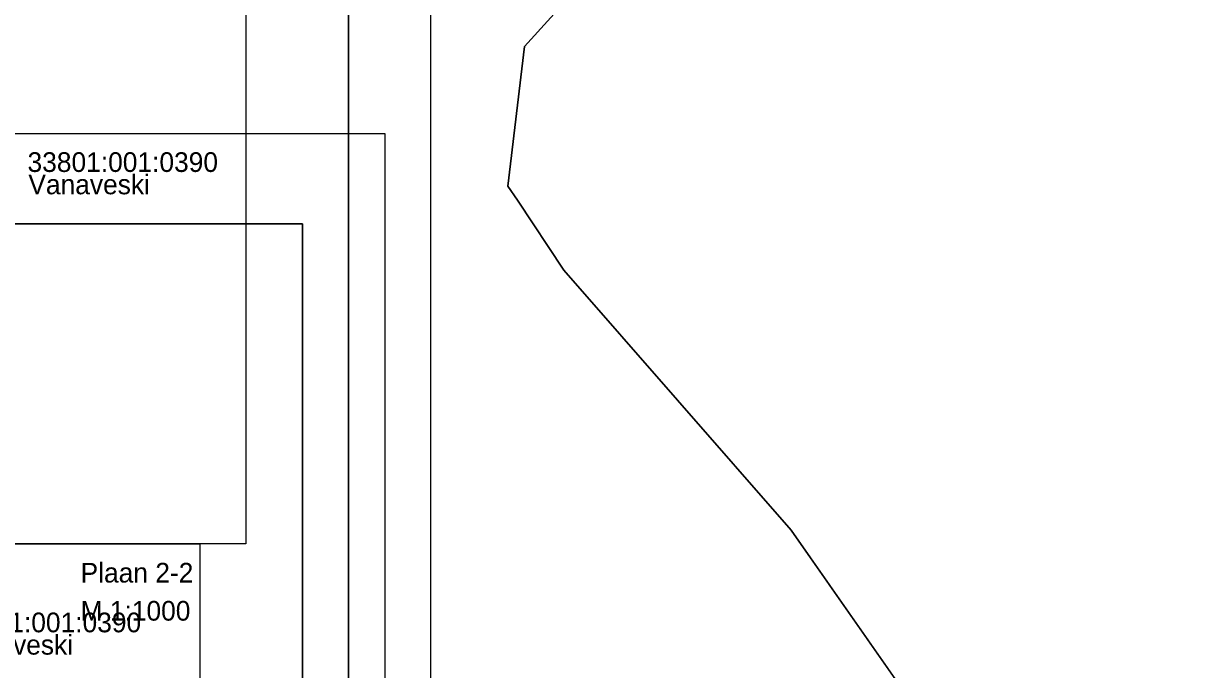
# Model space of a CAD drawing. Extents: x 554947 to 555436, y 6564938 to 6565792.
# Drawn here: x 555195.6 to 555338.1, y 6565169.6 to 6565248.3 of the extents above; entities that cross this region are included whole.
import ezdxf

# ---------------------------------------------------------------- set-up
doc = ezdxf.new("R2010")
doc.units = 0
for name, color, linetype in [('PIIR', 7, 'Continuous'), ('VORMISTUS', 7, 'Continuous'), ('VORMISTUS_1', 7, 'Continuous')]:
    doc.layers.add(name, color=color, linetype=linetype)

msp = doc.modelspace()

# ---------------------------------------------------------------- linework, layer by layer
at = {"layer": 'PIIR'}
for points in [[(555307.6, 6565160.1), (555289.11, 6565186.6), (555261.42, 6565218.27), (555255.75, 6565226.79), (555254.61, 6565228.5), (555256.63, 6565245.54), (555293.54, 6565286.23), (555292.52, 6565297.57), (555275.38, 6565300.17), (555205.15, 6565297.11), (555208.78, 6565303.3), (555303.13, 6565302.54), (555320.51, 6565314.61), (555338.12, 6565285.94)], [(555293.54, 6565286.23), (555256.63, 6565245.54), (555254.61, 6565228.5), (555255.75, 6565226.79), (555261.42, 6565218.27), (555289.11, 6565186.6), (555315.28, 6565149.09), (555315.73, 6565134.86), (555310.07, 6565124.47), (555303.59, 6565115.89), (555291.54, 6565100.48), (555288.85, 6565092.31), (555275.41, 6565088.83), (555273.15, 6565087.34), (555239.11, 6565139), (555231.12, 6565150.64), (555225.89, 6565157.13), (555173.21, 6565166.35), (555173.84, 6565168.77), (555191.64, 6565237.48), (555195.28, 6565271.63)]]:
    msp.add_lwpolyline(points, dxfattribs=at)
at = {"layer": 'VORMISTUS'}
for points in [[(555029.59, 6565234.91), (555239.59, 6565234.91), (555239.59, 6564937.91), (555029.59, 6564937.91)], [(555039.59, 6564948.91), (555229.59, 6564948.91), (555229.59, 6565223.91), (555039.59, 6565223.91)], [(555039.59, 6565223.91), (555229.59, 6565223.91), (555229.59, 6564948.91), (555039.59, 6564948.91)], [(555217.09, 6564974.91), (555052.09, 6564974.91), (555052.09, 6565184.91), (555217.09, 6565184.91)]]:
    msp.add_lwpolyline(points, close=True, dxfattribs=at)
at = {"layer": 'VORMISTUS_1'}
for points in [[(555035.19, 6565444.91), (555245.19, 6565444.91), (555245.19, 6565147.91), (555035.19, 6565147.91)], [(555045.19, 6565158.91), (555235.19, 6565158.91), (555235.19, 6565433.91), (555045.19, 6565433.91)], [(555045.19, 6565433.91), (555235.19, 6565433.91), (555235.19, 6565158.91), (555045.19, 6565158.91)], [(555222.69, 6565184.91), (555057.69, 6565184.91), (555057.69, 6565394.91), (555222.69, 6565394.91)]]:
    msp.add_lwpolyline(points, close=True, dxfattribs=at)

# ---------------------------------------------------------------- texts
at = {"layer": 'PIIR'}
for s, p in [('33801:001:0390', (555196.09, 6565230.24)), ('Vanaveski', (555196.19, 6565227.52)), ('33801:001:0390', (555186.73, 6565174.15)), ('Vanaveski', (555186.83, 6565171.43))]:
    msp.add_text(s, height=2.4, dxfattribs=at).set_placement(p)
at = {"layer": 'VORMISTUS_1'}
for s, p in [('Plaan 2-2', (555202.55, 6565180.21)), ('M 1:1000', (555202.55, 6565175.57))]:
    msp.add_text(s, height=2.4, rotation=360, dxfattribs=at).set_placement(p)

doc.saveas('drawing.dxf')
